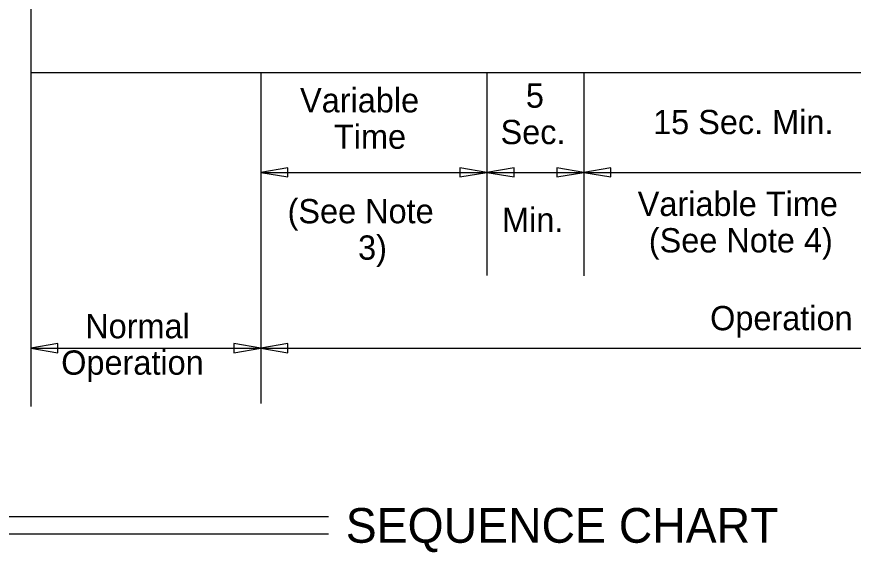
# Model space of a CAD drawing. Extents: x 15 to 764, y 7 to 487.
# Drawn here: x 460.7 to 581.3, y 26.4 to 103.6 of the extents above; entities that cross this region are included whole.
import ezdxf

# ---------------------------------------------------------------- set-up
doc = ezdxf.new("R2010")
doc.units = 0
for name, color, linetype in [('Default', 7, 'Continuous'), ('Dimension', 7, 'Continuous'), ('TextStructures', 7, 'Continuous')]:
    doc.layers.add(name, color=color, linetype=linetype)

msp = doc.modelspace()

# ---------------------------------------------------------------- linework, layer by layer
at = {"layer": 'Default'}
for p, q in [((462.69, 183.98), (462.69, 47.45)), ((462.69, 95.61), (756.61, 95.61)), ((495.88, 95.61), (495.88, 47.89)), ((528.47, 95.61), (528.47, 66.34)), ((542.46, 95.55), (542.46, 66.3)), ((495.88, 81.2), (528.47, 81.2)), ((528.47, 81.2), (542.46, 81.2)), ((542.46, 81.2), (593.57, 81.2)), ((462.69, 55.86), (495.88, 55.86)), ((495.88, 55.86), (720.58, 55.86))]:
    msp.add_line(p, q, dxfattribs=at)
at = {"layer": 'Dimension'}
for points in [[(495.88, 81.2), (499.78, 80.54), (499.78, 81.86)], [(528.47, 81.2), (524.57, 81.86), (524.57, 80.54)], [(528.47, 81.2), (532.38, 80.54), (532.38, 81.86)], [(542.46, 81.2), (538.55, 81.86), (538.55, 80.54)], [(542.46, 81.2), (546.36, 80.54), (546.36, 81.86)], [(462.69, 55.86), (466.59, 55.2), (466.59, 56.52)], [(495.88, 55.86), (491.97, 56.52), (491.97, 55.2)], [(495.88, 55.86), (499.78, 55.2), (499.78, 56.52)]]:
    msp.add_lwpolyline(points, close=True, dxfattribs=at)
at = {"layer": 'TextStructures'}
for p, q in [((505.61, 31.55), (330.42, 31.55)), ((505.61, 29.05), (330.42, 29.05))]:
    msp.add_line(p, q, dxfattribs=at)

# ---------------------------------------------------------------- texts
at = {"layer": 'Default'}
for s, p in [(' Variable Time', (548.92, 74.91)), ('(See Note 4)', (551.82, 69.66))]:
    msp.add_text(s, height=3.5, dxfattribs=at).set_placement(p)
at = {"layer": 'TextStructures'}
for s, height, p in [('Variable', 3.5, (501.52, 89.85)), (' 5', 3.5, (532.79, 90.52)), ('15 Sec. Min.', 3.5, (552.44, 86.71)), (' Time', 3.5, (505.11, 84.6)), ('Sec.', 3.5, (530.44, 85.27)), ('(See Note', 3.5, (499.72, 73.86)), ('Min.', 3.5, (530.66, 72.6)), (' 3)', 3.5, (508.59, 68.61)), ('Operation During Bridge Preemption', 3.5, (560.66, 58.44)), ('SEQUENCE CHART', 5, (508.11, 27.8))]:
    msp.add_text(s, height=height, dxfattribs=at).set_placement(p)
for s, p in [(' Normal', (469.23, 57.28)), ('Operation', (467.07, 52.03))]:
    msp.add_text(s, height=3.5, rotation=0.0007, dxfattribs=at).set_placement(p)

doc.saveas('drawing.dxf')
